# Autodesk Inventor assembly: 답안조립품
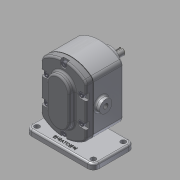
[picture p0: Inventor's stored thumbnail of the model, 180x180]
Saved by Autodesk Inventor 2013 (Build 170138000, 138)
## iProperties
Created: 2019-03
Part Number: 답안조립품
Document SubType Name: Assembly
Designer: Administrator
Author: Administrator
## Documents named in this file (11)
- C:\Users\Administrator\Desktop\490307V1009\답안조립품.iam
- C:\Users\Administrator\Desktop\490307V1009\본체.ipt
- C:\Users\Administrator\Desktop\490307V1009\메인축.ipt
- C:\Users\Administrator\Desktop\490307V1009\서브축.ipt
- C:\Users\Administrator\Desktop\490307V1009\키 6 x 6 x 18.ipt
- C:\Users\Administrator\Desktop\490307V1009\베어링부시.ipt
- C:\Users\Administrator\Desktop\490307V1009\개스킷.ipt
- C:\Users\Administrator\Desktop\490307V1009\볼트 M5.ipt
- C:\Users\Administrator\Desktop\490307V1009\스퍼기어.ipt
- C:\Users\Administrator\Desktop\490307V1009\오일 실 16 28 7.ipt
- C:\Users\Administrator\Desktop\490307V1009\커버.ipt
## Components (1 placed, 1 different names)
1. 개스킷:1
